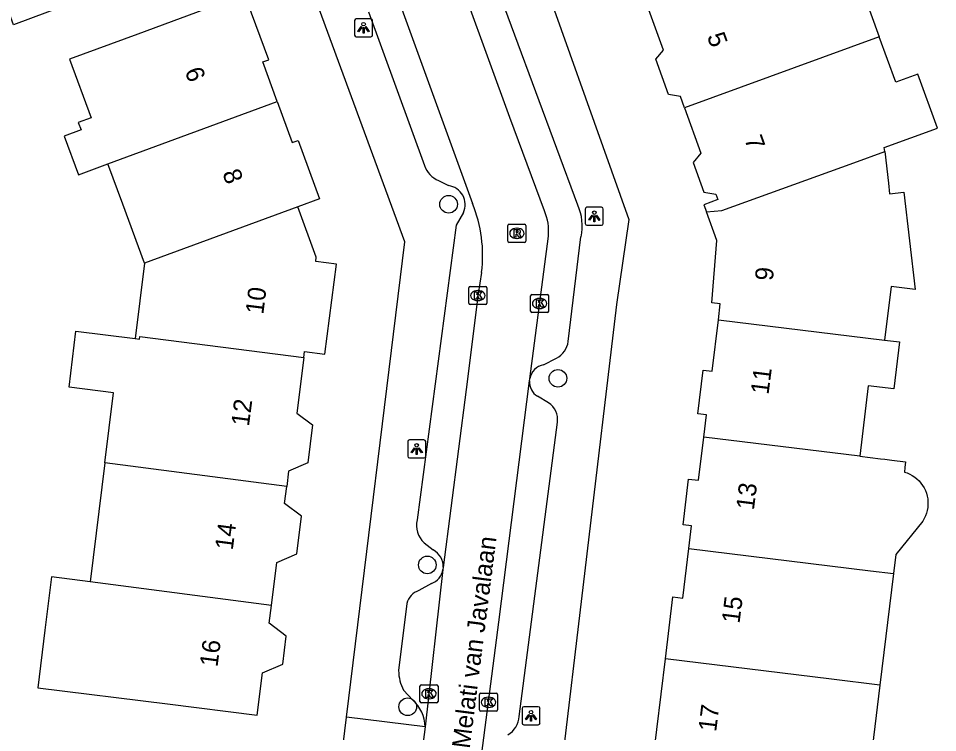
# Model space of a CAD drawing. Extents: x 161258 to 161838, y 380836 to 381727.
# Drawn here: x 161604.4 to 161655.3, y 381389 to 381428.6 of the extents above; entities that cross this region are included whole.
import ezdxf

# ---------------------------------------------------------------- set-up
doc = ezdxf.new("R2010")
doc.units = 0
for name, color, linetype in [('IMGEO_Boom', 7, 'Continuous'), ('IMGEO_Kolk', 7, 'Continuous'), ('IMGEO_Lichtpunt', 7, 'Continuous'), ('IMGEO_Openbare_ruimte_label', 7, 'Continuous'), ('IMGEO_Pand', 7, 'Continuous'), ('IMGEO_Pand_nummerreeks', 7, 'Continuous'), ('IMGEO_Rijbaan_lokaal_open', 7, 'Continuous'), ('IMGEO_Rioolput', 7, 'Continuous'), ('IMGEO_Voetpad_open', 7, 'Continuous')]:
    doc.layers.add(name, color=color, linetype=linetype)

msp = doc.modelspace()

# ---------------------------------------------------------------- linework, layer by layer
at = {"layer": 'IMGEO_Boom'}
for centre in [(161628.251, 381418.294), (161634.307, 381408.655), (161627.07, 381398.32), (161625.984, 381390.463)]:
    msp.add_circle(centre, 0.489, dxfattribs=at)
at = {"layer": 'IMGEO_Kolk'}
for p, q in [((161629.445, 381413.738), (161630.297, 381413.738)), ((161629.37, 381412.812), (161629.37, 381413.664)), ((161629.858, 381413.518), (161629.883, 381413.518)), ((161630.371, 381413.664), (161630.371, 381412.812)), ((161632.793, 381412.375), (161632.793, 381413.227)), ((161632.868, 381413.301), (161633.72, 381413.301)), ((161633.794, 381413.227), (161633.794, 381412.375)), ((161630.297, 381412.738), (161629.445, 381412.738)), ((161629.881, 381412.958), (161629.856, 381412.958)), ((161633.281, 381413.081), (161633.306, 381413.081)), ((161633.72, 381412.301), (161632.868, 381412.301)), ((161633.304, 381412.521), (161633.279, 381412.521)), ((161626.662, 381390.758), (161626.662, 381391.61)), ((161626.737, 381391.684), (161627.589, 381391.684)), ((161627.15, 381391.464), (161627.175, 381391.464)), ((161627.663, 381391.61), (161627.663, 381390.758)), ((161627.173, 381390.904), (161627.148, 381390.904)), ((161629.959, 381390.285), (161629.959, 381391.137)), ((161630.034, 381391.211), (161630.886, 381391.211)), ((161630.447, 381390.991), (161630.472, 381390.991)), ((161630.96, 381391.137), (161630.96, 381390.285)), ((161627.589, 381390.684), (161626.737, 381390.684)), ((161630.47, 381390.431), (161630.445, 381390.431)), ((161630.886, 381390.211), (161630.034, 381390.211))]:
    msp.add_line(p, q, dxfattribs=at)
for points in [[(161629.445, 381413.738), (161630.297, 381413.738)], [(161629.37, 381412.812), (161629.37, 381413.664)], [(161629.691, 381413.438), (161629.814, 381413.438), (161629.814, 381413.287), (161629.944, 381413.438), (161630.108, 381413.438), (161629.962, 381413.287), (161630.115, 381413.038), (161629.963, 381413.038), (161629.878, 381413.202), (161629.814, 381413.135), (161629.814, 381413.038), (161629.691, 381413.038), (161629.691, 381413.438)], [(161630.371, 381413.664), (161630.371, 381412.812)], [(161632.793, 381412.375), (161632.793, 381413.227)], [(161632.868, 381413.301), (161633.72, 381413.301)], [(161633.794, 381413.227), (161633.794, 381412.375)], [(161630.297, 381412.738), (161629.445, 381412.738)], [(161633.114, 381413.001), (161633.237, 381413.001), (161633.237, 381412.85), (161633.367, 381413.001), (161633.531, 381413.001), (161633.385, 381412.85), (161633.538, 381412.601), (161633.386, 381412.601), (161633.301, 381412.765), (161633.237, 381412.698), (161633.237, 381412.601), (161633.114, 381412.601), (161633.114, 381413.001)], [(161633.72, 381412.301), (161632.868, 381412.301)], [(161626.662, 381390.758), (161626.662, 381391.61)], [(161626.737, 381391.684), (161627.589, 381391.684)], [(161626.983, 381391.384), (161627.106, 381391.384), (161627.106, 381391.233), (161627.236, 381391.384), (161627.4, 381391.384), (161627.254, 381391.233), (161627.407, 381390.984), (161627.255, 381390.984), (161627.17, 381391.148), (161627.106, 381391.081), (161627.106, 381390.984), (161626.983, 381390.984), (161626.983, 381391.384)], [(161627.663, 381391.61), (161627.663, 381390.758)], [(161629.959, 381390.285), (161629.959, 381391.137)], [(161630.034, 381391.211), (161630.886, 381391.211)], [(161630.28, 381390.911), (161630.403, 381390.911), (161630.403, 381390.76), (161630.533, 381390.911), (161630.697, 381390.911), (161630.551, 381390.76), (161630.704, 381390.511), (161630.552, 381390.511), (161630.467, 381390.675), (161630.403, 381390.608), (161630.403, 381390.511), (161630.28, 381390.511), (161630.28, 381390.911)], [(161630.96, 381391.137), (161630.96, 381390.285)], [(161627.589, 381390.684), (161626.737, 381390.684)], [(161630.886, 381390.211), (161630.034, 381390.211)]]:
    msp.add_lwpolyline(points, dxfattribs=at)
for centre, start, end in [((161629.447, 381413.662), 91.552, 178.448), ((161629.447, 381413.662), 91.552, 178.448), ((161630.295, 381413.662), 1.552, 88.448), ((161630.295, 381413.662), 1.552, 88.448), ((161632.87, 381413.225), 91.552, 178.448), ((161632.87, 381413.225), 91.552, 178.448), ((161633.718, 381413.225), 1.552, 88.448), ((161633.718, 381413.225), 1.552, 88.448), ((161629.447, 381412.814), 181.552, 268.448), ((161629.447, 381412.814), 181.552, 268.448), ((161630.295, 381412.814), 271.552, 358.448), ((161630.295, 381412.814), 271.552, 358.448), ((161632.87, 381412.377), 181.552, 268.448), ((161632.87, 381412.377), 181.552, 268.448), ((161633.718, 381412.377), 271.552, 358.448), ((161633.718, 381412.377), 271.552, 358.448), ((161626.739, 381391.608), 91.552, 178.448), ((161626.739, 381391.608), 91.552, 178.448), ((161627.587, 381391.608), 1.552, 88.448), ((161627.587, 381391.608), 1.552, 88.448), ((161626.739, 381390.76), 181.552, 268.448), ((161626.739, 381390.76), 181.552, 268.448), ((161627.587, 381390.76), 271.552, 358.448), ((161627.587, 381390.76), 271.552, 358.448), ((161630.036, 381391.135), 91.552, 178.448), ((161630.036, 381391.135), 91.552, 178.448), ((161630.884, 381391.135), 1.552, 88.448), ((161630.884, 381391.135), 1.552, 88.448), ((161630.036, 381390.287), 181.552, 268.448), ((161630.036, 381390.287), 181.552, 268.448), ((161630.884, 381390.287), 271.552, 358.448), ((161630.884, 381390.287), 271.552, 358.448)]:
    msp.add_arc(centre, 0.0765, start, end, dxfattribs=at)
for centre, major_axis, ratio, start_param, end_param in [((161629.857, 381413.238), (-0.387, 0.002), 0.722429, 4.712389, 7.853982), ((161629.882, 381413.238), (-0.39, 0.002), 0.717154, 1.570796, 4.712389), ((161633.28, 381412.801), (-0.387, 0.002), 0.722429, 4.712389, 7.853982), ((161633.305, 381412.801), (-0.39, 0.002), 0.717154, 1.570796, 4.712389), ((161627.149, 381391.184), (-0.387, 0.002), 0.722429, 4.712389, 7.853982), ((161627.174, 381391.184), (-0.39, 0.002), 0.717154, 1.570796, 4.712389), ((161630.446, 381390.711), (-0.387, 0.002), 0.722429, 4.712389, 7.853982), ((161630.471, 381390.711), (-0.39, 0.002), 0.717154, 1.570796, 4.712389)]:
    msp.add_ellipse(centre, major_axis=major_axis, ratio=ratio, start_param=start_param, end_param=end_param, dxfattribs=at)
at = {"layer": 'IMGEO_Lichtpunt'}
for p, q in [((161623.039, 381428.472), (161623.039, 381427.665)), ((161623.039, 381428.472), (161623.039, 381427.665)), ((161623.941, 381428.567), (161623.133, 381428.567)), ((161623.941, 381428.567), (161623.133, 381428.567)), ((161624.035, 381427.665), (161624.035, 381428.472)), ((161624.035, 381427.665), (161624.035, 381428.472)), ((161623.133, 381427.571), (161623.941, 381427.571)), ((161623.133, 381427.571), (161623.941, 381427.571)), ((161635.824, 381418.033), (161635.824, 381417.226)), ((161635.824, 381418.033), (161635.824, 381417.226)), ((161636.726, 381418.128), (161635.918, 381418.128)), ((161636.726, 381418.128), (161635.918, 381418.128)), ((161636.82, 381417.226), (161636.82, 381418.033)), ((161636.82, 381417.226), (161636.82, 381418.033)), ((161635.918, 381417.132), (161636.726, 381417.132)), ((161635.918, 381417.132), (161636.726, 381417.132)), ((161625.983, 381405.148), (161625.983, 381404.341)), ((161625.983, 381405.148), (161625.983, 381404.341)), ((161626.885, 381405.243), (161626.077, 381405.243)), ((161626.885, 381405.243), (161626.077, 381405.243)), ((161626.979, 381404.341), (161626.979, 381405.148)), ((161626.979, 381404.341), (161626.979, 381405.148)), ((161626.077, 381404.247), (161626.885, 381404.247)), ((161626.077, 381404.247), (161626.885, 381404.247)), ((161632.318, 381390.367), (161632.318, 381389.56)), ((161632.318, 381390.367), (161632.318, 381389.56)), ((161633.22, 381390.462), (161632.412, 381390.462)), ((161633.22, 381390.462), (161632.412, 381390.462)), ((161633.314, 381389.56), (161633.314, 381390.367)), ((161633.314, 381389.56), (161633.314, 381390.367)), ((161632.412, 381389.466), (161633.22, 381389.466)), ((161632.412, 381389.466), (161633.22, 381389.466))]:
    msp.add_line(p, q, dxfattribs=at)
for points in [[(161623.413, 381428.136), (161623.452, 381428.108), (161623.264, 381427.846), (161623.226, 381427.873), (161623.413, 381428.136)], [(161623.515, 381428.088), (161623.562, 381428.088), (161623.562, 381427.766), (161623.515, 381427.766), (161623.515, 381428.088)], [(161623.625, 381428.108), (161623.663, 381428.135), (161623.85, 381427.873), (161623.811, 381427.845), (161623.625, 381428.108)], [(161636.198, 381417.697), (161636.237, 381417.669), (161636.049, 381417.407), (161636.011, 381417.434), (161636.198, 381417.697)], [(161636.3, 381417.649), (161636.347, 381417.649), (161636.347, 381417.327), (161636.3, 381417.327), (161636.3, 381417.649)], [(161636.41, 381417.669), (161636.448, 381417.696), (161636.635, 381417.434), (161636.596, 381417.406), (161636.41, 381417.669)], [(161626.357, 381404.812), (161626.396, 381404.784), (161626.208, 381404.522), (161626.17, 381404.549), (161626.357, 381404.812)], [(161626.459, 381404.764), (161626.506, 381404.764), (161626.506, 381404.442), (161626.459, 381404.442), (161626.459, 381404.764)], [(161626.569, 381404.784), (161626.607, 381404.811), (161626.794, 381404.549), (161626.755, 381404.521), (161626.569, 381404.784)], [(161632.692, 381390.031), (161632.731, 381390.003), (161632.543, 381389.741), (161632.505, 381389.768), (161632.692, 381390.031)], [(161632.794, 381389.983), (161632.841, 381389.983), (161632.841, 381389.661), (161632.794, 381389.661), (161632.794, 381389.983)], [(161632.904, 381390.003), (161632.942, 381390.03), (161633.129, 381389.768), (161633.09, 381389.74), (161632.904, 381390.003)]]:
    msp.add_lwpolyline(points, dxfattribs=at)
for centre in [(161623.538, 381428.27), (161636.323, 381417.831), (161626.482, 381404.946), (161632.817, 381390.165)]:
    msp.add_circle(centre, 0.0994, dxfattribs=at)
for centre, start, end in [((161623.133, 381428.472), 90, 180), ((161623.133, 381428.472), 90, 180), ((161623.941, 381428.472), 0, 90), ((161623.941, 381428.472), 0, 90), ((161623.133, 381427.665), 180, 270), ((161623.133, 381427.665), 180, 270), ((161623.941, 381427.665), 270, 0), ((161623.941, 381427.665), 270, 360), ((161635.918, 381418.033), 90, 180), ((161635.918, 381418.033), 90, 180), ((161636.726, 381418.033), 0, 90), ((161636.726, 381418.033), 0, 90), ((161635.918, 381417.226), 180, 270), ((161635.918, 381417.226), 180, 270), ((161636.726, 381417.226), 270, 0), ((161636.726, 381417.226), 270, 360), ((161626.077, 381405.148), 90, 180), ((161626.077, 381405.148), 90, 180), ((161626.885, 381405.148), 0, 90), ((161626.885, 381405.148), 0, 90), ((161626.077, 381404.341), 180, 270), ((161626.077, 381404.341), 180, 270), ((161626.885, 381404.341), 270, 0), ((161626.885, 381404.341), 270, 360), ((161632.412, 381390.367), 90, 180), ((161632.412, 381390.367), 90, 180), ((161633.22, 381390.367), 0, 90), ((161633.22, 381390.367), 0, 90), ((161632.412, 381389.56), 180, 270), ((161632.412, 381389.56), 180, 270), ((161633.22, 381389.56), 270, 0), ((161633.22, 381389.56), 270, 360)]:
    msp.add_arc(centre, 0.0946, start, end, dxfattribs=at)
at = {"layer": 'IMGEO_Pand'}
for points in [[(161650.5, 381433.278), (161651.513, 381430.483), (161651.111, 381430.337), (161652.116, 381427.564)], [(161606.966, 381429.283), (161604.141, 381428.241), (161602.945, 381431.483)], [(161618.756, 381423.997), (161617.959, 381426.177), (161618.288, 381426.298), (161617.095, 381429.532), (161615.858, 381429.075), (161615.722, 381429.445), (161611.031, 381427.715), (161607.245, 381426.324), (161608.439, 381423.08), (161607.73, 381422.818), (161607.88, 381422.411), (161606.945, 381422.066), (161607.734, 381419.929), (161609.375, 381420.535)], [(161641.325, 381423.633), (161641.098, 381424.258), (161640.441, 381424.374), (161639.732, 381426.332), (161640.15, 381426.829), (161639.267, 381429.267)], [(161652.116, 381427.564), (161641.325, 381423.633)], [(161652.417, 381421.224), (161652.393, 381421.433), (161655.347, 381422.504), (161654.26, 381425.502), (161653.026, 381425.055), (161652.116, 381427.564)], [(161609.375, 381420.535), (161618.756, 381423.997)], [(161618.756, 381423.997), (161619.588, 381421.723), (161619.914, 381421.837), (161621.096, 381418.604), (161619.886, 381418.157)], [(161641.325, 381423.633), (161642.231, 381421.131), (161641.796, 381420.614), (161642.393, 381418.967), (161643.066, 381418.847), (161643.172, 381418.556), (161642.393, 381418.273), (161642.538, 381417.874)], [(161642.538, 381417.874), (161643.389, 381417.942), (161650.698, 381420.599), (161652.417, 381421.224)], [(161652.417, 381421.224), (161652.622, 381419.465), (161652.689, 381418.882), (161653.481, 381418.974), (161654.109, 381413.568), (161652.773, 381413.747), (161652.411, 381410.773)], [(161611.402, 381415.027), (161610.2, 381418.293), (161609.375, 381420.535)], [(161619.886, 381418.157), (161611.402, 381415.027)], [(161620.224, 381409.8), (161620.266, 381410.138), (161621.383, 381409.991), (161622.04, 381414.971), (161620.888, 381415.131), (161620.917, 381415.363), (161619.886, 381418.157)], [(161643.197, 381411.896), (161643.305, 381412.783), (161642.836, 381412.841), (161643.11, 381416.297), (161642.538, 381417.874)], [(161611.402, 381415.027), (161610.885, 381410.86)], [(161642.387, 381405.397), (161642.537, 381406.626), (161642.057, 381406.684), (161642.353, 381409.109), (161642.85, 381409.049), (161643.197, 381411.896)], [(161643.197, 381411.896), (161652.411, 381410.773)], [(161609.206, 381403.969), (161609.689, 381407.854), (161607.215, 381408.173), (161607.601, 381411.267), (161610.885, 381410.86)], [(161610.885, 381410.86), (161611.123, 381410.83), (161611.14, 381410.972), (161620.224, 381409.8)], [(161652.411, 381410.773), (161653.244, 381410.672), (161652.927, 381408.067), (161651.505, 381408.24), (161651.03, 381404.344)], [(161620.224, 381409.8), (161619.842, 381406.729), (161620.711, 381406.072), (161620.449, 381403.966), (161619.387, 381403.518), (161619.281, 381402.669)], [(161641.557, 381399.223), (161641.711, 381400.485), (161641.243, 381400.542), (161641.552, 381403.076), (161642.096, 381403.01), (161642.387, 381405.397)], [(161651.03, 381404.344), (161642.387, 381405.397)], [(161651.03, 381404.344), (161652.184, 381404.204), (161652.428, 381404.174), (161652.812, 381404.127), (161653.574, 381404.034), (161653.536, 381403.723), (161653.505, 381403.466), (161653.657, 381403.414), (161653.804, 381403.35), (161653.945, 381403.273), (161654.078, 381403.183), (161654.203, 381403.082), (161654.318, 381402.971), (161654.423, 381402.85), (161654.517, 381402.719), (161654.599, 381402.582), (161654.668, 381402.437), (161654.725, 381402.287), (161654.767, 381402.132), (161654.796, 381401.974), (161654.811, 381401.815), (161654.812, 381401.654), (161654.798, 381401.494), (161654.771, 381401.336), (161654.729, 381401.181), (161654.674, 381401.031), (161654.606, 381400.886), (161654.525, 381400.747), (161653.031, 381398.9), (161652.902, 381397.839)], [(161609.206, 381403.969), (161608.385, 381397.376)], [(161619.281, 381402.669), (161609.206, 381403.969)], [(161618.431, 381396.079), (161618.727, 381398.457), (161619.836, 381398.926), (161620.095, 381401.011), (161619.163, 381401.716), (161619.281, 381402.669)], [(161640.266, 381393.111), (161640.684, 381396.544), (161641.223, 381396.478), (161641.557, 381399.223)], [(161641.557, 381399.223), (161651.632, 381397.994), (161652.902, 381397.839)], [(161608.385, 381397.376), (161606.25, 381397.651), (161605.884, 381394.71), (161605.486, 381391.514), (161612.678, 381390.619), (161617.639, 381390.002), (161617.931, 381392.349), (161619.06, 381392.826), (161619.253, 381394.375), (161618.308, 381395.089), (161618.431, 381396.079)], [(161618.431, 381396.079), (161608.385, 381397.376)], [(161652.902, 381397.839), (161652.148, 381391.662)], [(161652.148, 381391.662), (161651.795, 381388.769), (161651.432, 381385.79), (161644.514, 381386.633), (161639.55, 381387.238), (161640.266, 381393.111)], [(161652.148, 381391.662), (161649.467, 381391.989), (161640.266, 381393.111)]]:
    msp.add_lwpolyline(points, dxfattribs=at)
at = {"layer": 'IMGEO_Rijbaan_lokaal_open'}
for points in [[(161633.562, 381417.932), (161631.642, 381423.104), (161628.071, 381432.908)], [(161624.621, 381431.971), (161629.58, 381418.332)], [(161632.744, 381408.636), (161633.782, 381416.523)], [(161630.074, 381414.521), (161629.886, 381413.343), (161629.229, 381408.041), (161627.951, 381398.186)], [(161632.729, 381408.516), (161632.744, 381408.636)], [(161630.024, 381387.329), (161631.028, 381395.148), (161632.729, 381408.516)], [(161627.937, 381398.058), (161626.958, 381389.351)], [(161627.951, 381398.186), (161627.937, 381398.058)], [(161626.958, 381389.351), (161626.112, 381382.98)]]:
    msp.add_lwpolyline(points, dxfattribs=at)
for centre, radius, start, end in [((161622.538, 381415.482), 7.597, 352.7345, 22.0371), ((161630.83, 381416.784), 2.964, 354.9531, 22.7958)]:
    msp.add_arc(centre, radius, start, end, dxfattribs=at)
at = {"layer": 'IMGEO_Rioolput'}
for p, q in [((161631.535, 381416.261), (161631.535, 381417.113)), ((161631.61, 381417.187), (161632.462, 381417.187)), ((161632.023, 381416.967), (161632.048, 381416.967)), ((161632.536, 381417.113), (161632.536, 381416.261)), ((161632.046, 381416.407), (161632.021, 381416.407)), ((161632.462, 381416.187), (161631.61, 381416.187))]:
    msp.add_line(p, q, dxfattribs=at)
for points in [[(161631.535, 381416.261), (161631.535, 381417.113)], [(161631.61, 381417.187), (161632.462, 381417.187)], [(161632.124, 381416.885), (161631.872, 381416.887), (161631.872, 381416.487)], [(161632.05, 381416.806), (161631.996, 381416.806), (161631.996, 381416.725)], [(161631.996, 381416.725), (161632.048, 381416.725)], [(161632.536, 381417.113), (161632.536, 381416.261)], [(161631.872, 381416.487), (161631.996, 381416.487), (161631.996, 381416.649), (161632.007, 381416.649)], [(161632.054, 381416.62), (161632.125, 381416.487), (161632.265, 381416.487), (161632.2, 381416.613)], [(161632.462, 381416.187), (161631.61, 381416.187)]]:
    msp.add_lwpolyline(points, dxfattribs=at)
for centre, radius, start, end in [((161631.612, 381417.111), 0.0765, 91.552, 178.448), ((161631.612, 381417.111), 0.0765, 91.552, 178.448), ((161632.032, 381416.914), 0.19, 274.7715, 282.9687), ((161632.056, 381416.71), 0.0964, 77.0061, 93.1865), ((161632.07, 381416.767), 0.0378, 276.6634, 79.6772), ((161632.123, 381416.775), 0.109, 350.3612, 89.416), ((161632.121, 381416.775), 0.112, 277.5842, 350.9817), ((161632.46, 381417.111), 0.0765, 1.552, 88.448), ((161632.46, 381417.111), 0.0765, 1.552, 88.448), ((161631.612, 381416.263), 0.0765, 181.552, 268.448), ((161631.612, 381416.263), 0.0765, 181.552, 268.448), ((161632.006, 381416.596), 0.0533, 26.0293, 88.6989), ((161632.105, 381416.56), 0.108, 29.5134, 73.7905), ((161632.46, 381416.263), 0.0765, 271.552, 358.448), ((161632.46, 381416.263), 0.0765, 271.552, 358.448)]:
    msp.add_arc(centre, radius, start, end, dxfattribs=at)
for centre, major_axis, ratio, start_param, end_param in [((161632.022, 381416.687), (-0.387, 0.002), 0.722429, 4.712389, 7.853982), ((161632.047, 381416.687), (-0.39, 0.002), 0.717154, 1.570796, 4.712389)]:
    msp.add_ellipse(centre, major_axis=major_axis, ratio=ratio, start_param=start_param, end_param=end_param, dxfattribs=at)
at = {"layer": 'IMGEO_Voetpad_open'}
for points in [[(161632.557, 381433.385), (161638.239, 381417.444), (161637.547, 381412.742), (161634.273, 381385.117)], [(161622.597, 381389.891), (161625.828, 381416.218), (161620.508, 381430.682)], [(161635.402, 381418.251), (161630.754, 381430.823)], [(161623.816, 381428.956), (161626.919, 381420.439)], [(161627.69, 381419.611), (161628.247, 381419.33)], [(161629.067, 381417.842), (161628.67, 381417.132), (161626.501, 381400.815)], [(161634.878, 381410.7), (161635.586, 381416.499)], [(161633.515, 381409.397), (161634.227, 381409.775)], [(161633.786, 381407.301), (161633.178, 381407.659)], [(161632.158, 381389.928), (161634.277, 381406.221)], [(161626.889, 381399.544), (161627.395, 381399.148)], [(161627.299, 381397.283), (161626.6, 381396.904)], [(161625.937, 381396.183), (161625.479, 381392.465)], [(161625.754, 381391.385), (161626.259, 381390.837)], [(161621.814, 381383.511), (161622.597, 381389.891)], [(161626.958, 381389.351), (161622.597, 381389.891)]]:
    msp.add_lwpolyline(points, dxfattribs=at)
for centre, radius, start, end in [((161628.219, 381420.877), 1.372, 198.6057, 247.3111), ((161628.104, 381418.281), 1.059, 335.4871, 82.229), ((161632.957, 381417.109), 2.699, 346.9493, 25.0415), ((161633.669, 381410.859), 1.219, 297.2181, 352.5074), ((161633.674, 381408.465), 0.946, 99.6962, 169.5558), ((161633.676, 381408.466), 0.949, 176.9886, 238.3133), ((161633.196, 381406.381), 1.093, 351.5745, 57.3214), ((161627.822, 381400.523), 1.352, 167.5514, 226.4005), ((161626.922, 381398.233), 1.03, 357.3973, 62.6554), ((161626.927, 381398.24), 1.027, 291.2721, 349.8037), ((161626.915, 381395.949), 1.005, 108.2424, 166.5571), ((161627.848, 381392.493), 2.369, 180.684, 207.8872), ((161624.835, 381389.26), 2.125, 2.457, 47.9267), ((161630.92, 381389.992), 1.239, 299.5721, 357.0491)]:
    msp.add_arc(centre, radius, start, end, dxfattribs=at)

# ---------------------------------------------------------------- texts
at = {"layer": 'IMGEO_Openbare_ruimte_label'}
msp.add_text('Melati van Javalaan', height=1, rotation=82.7613, dxfattribs=at).set_placement((161629.419, 381388.115))
at = {"layer": 'IMGEO_Pand_nummerreeks'}
for s, rotation, p in [('5', 289.9821, (161642.554, 381427.606)), ('6', 290.2496, (161613.616, 381425.678)), ('7', 289.9846, (161644.626, 381421.908)), ('8', 290.2481, (161615.7, 381420.03)), ('9', 85.4681, (161646.221, 381414.035)), ('10', 82.9013, (161617.979, 381412.166)), ('11', 82.7695, (161645.974, 381407.724)), ('12', 82.5518, (161617.182, 381405.964)), ('13', 82.7695, (161645.163, 381401.328)), ('14', 82.5518, (161616.286, 381399.107)), ('15', 82.7695, (161644.366, 381395.044)), ('16', 82.5747, (161615.441, 381392.637)), ('17', 83.0524, (161643.075, 381389.048))]:
    msp.add_text(s, height=1, rotation=rotation, dxfattribs=at).set_placement(p)

doc.saveas('drawing.dxf')
